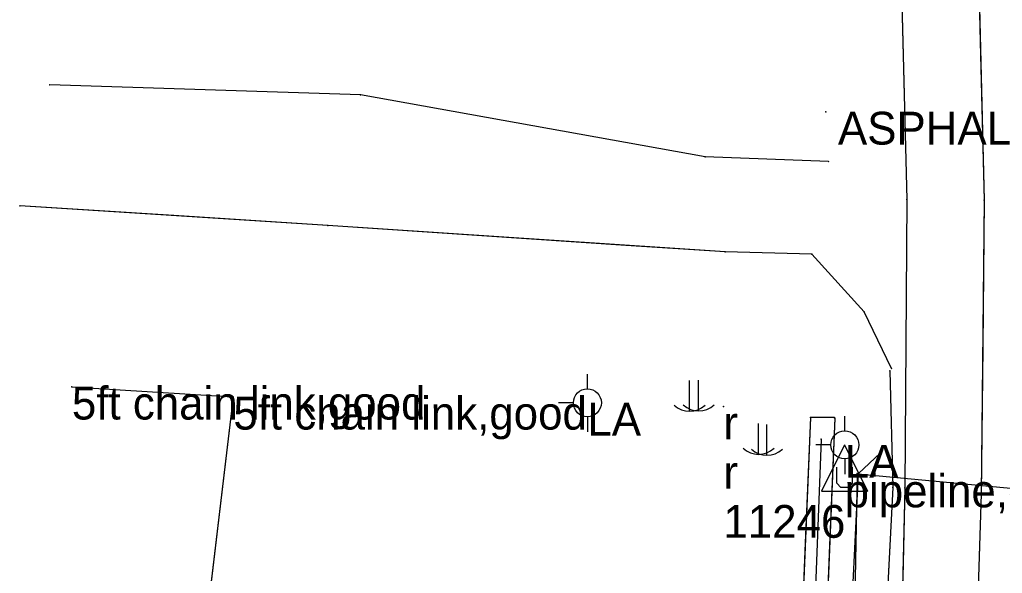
# Model space of a CAD drawing. Extents: x -99999 to 591807, y -99999 to 347168.
# Drawn here: x 591113.2 to 591263, y 320901.3 to 320985.6 of the extents above; entities that cross this region are included whole.
import ezdxf

# ---------------------------------------------------------------- set-up
doc = ezdxf.new("R2010")
doc.units = 0
for name, color, linetype in [('Default', 7, 'Continuous'), ('S_BREAKLINE', 7, 'Continuous'), ('S_DITCHLINE', 7, 'Continuous'), ('S_DRIVEWAY', 7, 'Continuous'), ('S_EDGE_PAVEMENT', 7, 'Continuous'), ('S_FENCE', 7, 'Continuous'), ('S_FENCE_ANNOT', 7, 'Continuous'), ('S_GAS_UTILITIES', 7, 'Continuous'), ('S_GRD_PT_SYM', 7, 'Continuous'), ('S_MSC_PT_SYM', 7, 'Continuous'), ('S_PARKING', 7, 'Continuous'), ('S_PAVEMENT_CROWN', 7, 'Continuous'), ('S_RDW_PT_SYM', 7, 'Continuous'), ('S_SHOULDER', 7, 'Continuous'), ('S_SIDEWALK', 7, 'Continuous'), ('S_SURVEY_TEXT_ANNOT', 7, 'Continuous'), ('S_UTILITY_POLE', 7, 'Continuous'), ('S_UTILITY_POLE_ANNOT', 7, 'Continuous'), ('S_UTL_PT_SYM', 7, 'Continuous'), ('S_WATER_UTILITIES', 7, 'Continuous')]:
    doc.layers.add(name, color=color, linetype=linetype)

msp = doc.modelspace()

# ---------------------------------------------------------------- linework, layer by layer
at = {"layer": 'Default'}
msp.add_lwpolyline([(591220.51, 320926.7), (591220.51, 320926.75), (591220.51, 320926.7), (591220.46, 320926.7), (591220.51, 320926.7), (591220.51, 320926.65), (591220.51, 320926.7), (591220.56, 320926.7)], dxfattribs=at)
at = {"layer": 'S_BREAKLINE'}
msp.add_lwpolyline([(591236.51, 320964.02), (591217.74, 320964.73), (591165.18, 320974.2), (591117.8, 320975.7)], dxfattribs=at)
at = {"layer": 'S_DITCHLINE'}
msp.add_lwpolyline([(591239.28, 320879.11), (591240.19, 320897.8), (591241.11, 320916.49), (591244.41, 320919.57)], dxfattribs=at)
at = {"layer": 'S_DRIVEWAY'}
msp.add_lwpolyline([(591246.15, 320932.47), (591241.98, 320941.14), (591233.98, 320949.92), (591220.76, 320950.28)], dxfattribs=at)
msp.add_lwpolyline([(591246.15, 320932.47), (591241.98, 320941.14), (591233.98, 320949.92), (591220.76, 320950.28)], dxfattribs=at)
at = {"layer": 'S_EDGE_PAVEMENT'}
for points in [[(591157.82, 321374.56), (591172, 321326.2), (591184.5, 321283.67), (591196.97, 321241.41), (591212.28, 321187.83), (591223.28, 321148.22), (591233.12, 321106.87), (591242.97, 321050.29), (591247.28, 321006.15), (591248.49, 320958.25), (591248.17, 320914.3), (591247.12, 320868.72), (591245.56, 320824.19), (591244.17, 320785.58), (591242.25, 320742.56), (591240.73, 320705.61), (591238.92, 320663.7), (591237.27, 320623.33), (591235.85, 320588.31), (591234.3, 320543.12), (591232.69, 320503.41), (591231.22, 320460.43), (591229.56, 320424.54)], [(591223.28, 321148.22), (591228.2, 321127.55), (591233.12, 321106.87), (591235.58, 321092.73), (591238.04, 321078.58), (591240.51, 321064.44), (591242.97, 321050.29), (591245.13, 321028.22), (591247.28, 321006.15), (591247.88, 320982.2), (591248.49, 320958.25), (591248.33, 320936.28), (591248.17, 320914.3), (591247.64, 320891.51)]]:
    msp.add_lwpolyline(points, dxfattribs=at)
at = {"layer": 'S_FENCE'}
for p, q in [((591121.19, 320929.72), (591145.8, 320928.19)), ((591145.8, 320928.19), (591140.22, 320881.7))]:
    msp.add_line(p, q, dxfattribs=at)
for points in [[(591121.19, 320929.72), (591145.8, 320928.19)], [(591145.8, 320928.19), (591140.22, 320881.7)]]:
    msp.add_lwpolyline(points, dxfattribs=at)
at = {"layer": 'S_GAS_UTILITIES'}
for p, q in [((591240.88, 320916.49), (591239.82, 320856.4)), ((591279.22, 320912.81), (591240.99, 320916.41))]:
    msp.add_line(p, q, dxfattribs=at)
at = {"layer": 'S_GRD_PT_SYM'}
for points in [[(591117.8, 320975.7), (591117.8, 320975.65), (591117.8, 320975.7), (591117.85, 320975.69), (591117.8, 320975.7), (591117.81, 320975.75), (591117.8, 320975.7), (591117.75, 320975.7)], [(591165.18, 320974.2), (591165.18, 320974.15), (591165.18, 320974.2), (591165.23, 320974.2), (591165.18, 320974.2), (591165.18, 320974.25), (591165.18, 320974.2), (591165.13, 320974.2)], [(591217.74, 320964.73), (591217.73, 320964.68), (591217.74, 320964.73), (591217.78, 320964.72), (591217.74, 320964.73), (591217.74, 320964.78), (591217.74, 320964.73), (591217.69, 320964.74)], [(591236.51, 320964.02), (591236.5, 320963.97), (591236.51, 320964.02), (591236.56, 320964.01), (591236.51, 320964.02), (591236.51, 320964.07), (591236.51, 320964.02), (591236.46, 320964.02)]]:
    msp.add_lwpolyline(points, close=True, dxfattribs=at)
at = {"layer": 'S_MSC_PT_SYM'}
for points in [[(591236.12, 320971.61), (591236.12, 320971.66), (591236.12, 320971.61), (591236.07, 320971.61), (591236.12, 320971.61), (591236.12, 320971.56), (591236.12, 320971.61), (591236.17, 320971.61)], [(591121.19, 320929.72), (591121.19, 320929.77), (591121.19, 320929.72), (591121.14, 320929.72), (591121.19, 320929.72), (591121.19, 320929.67), (591121.19, 320929.72), (591121.24, 320929.72)], [(591145.8, 320928.19), (591145.8, 320928.24), (591145.8, 320928.19), (591145.75, 320928.19), (591145.8, 320928.19), (591145.8, 320928.14), (591145.8, 320928.19), (591145.85, 320928.19)]]:
    msp.add_lwpolyline(points, dxfattribs=at)
for points in [[(591113.27, 320957.3), (591113.27, 320957.25), (591113.27, 320957.3), (591113.32, 320957.3), (591113.27, 320957.3), (591113.28, 320957.35), (591113.27, 320957.3), (591113.22, 320957.31)], [(591160.19, 320954.26), (591160.19, 320954.21), (591160.19, 320954.26), (591160.24, 320954.26), (591160.19, 320954.26), (591160.2, 320954.31), (591160.19, 320954.26), (591160.14, 320954.26)], [(591220.76, 320950.25), (591220.75, 320950.2), (591220.76, 320950.25), (591220.81, 320950.25), (591220.76, 320950.25), (591220.76, 320950.3), (591220.76, 320950.25), (591220.71, 320950.25)], [(591233.78, 320925.02), (591233.83, 320925.02), (591233.78, 320925.02), (591233.79, 320925.07), (591233.78, 320925.02), (591233.73, 320925.02), (591233.78, 320925.02), (591233.78, 320924.97)], [(591237.39, 320925.01), (591237.39, 320924.96), (591237.39, 320925.01), (591237.44, 320925.01), (591237.39, 320925.01), (591237.39, 320925.06), (591237.39, 320925.01), (591237.34, 320925.01)], [(591237.48, 320924.93), (591237.53, 320924.93), (591237.48, 320924.93), (591237.48, 320924.98), (591237.48, 320924.93), (591237.43, 320924.93), (591237.48, 320924.93), (591237.48, 320924.88)]]:
    msp.add_lwpolyline(points, close=True, dxfattribs=at)
at = {"layer": 'S_PARKING'}
for points in [[(591220.76, 320950.25), (591160.19, 320954.26), (591113.27, 320957.3)], [(591220.76, 320950.25), (591205.62, 320951.25), (591190.47, 320952.25), (591175.33, 320953.26), (591160.19, 320954.26), (591136.73, 320955.78), (591113.27, 320957.3)]]:
    msp.add_lwpolyline(points, dxfattribs=at)
at = {"layer": 'S_PAVEMENT_CROWN'}
for points in [[(591169.39, 321376.17), (591182.7, 321330.3), (591196.05, 321285.51), (591208.23, 321244.2), (591224.14, 321189.5), (591234.43, 321151.84), (591245.74, 321106.05), (591255.46, 321050.58), (591259.1, 321006.38), (591260.26, 320958.14), (591259.83, 320913.41), (591258.41, 320868.94), (591257.04, 320823.07), (591255.42, 320785.26), (591253.78, 320741.8), (591252.12, 320704.89), (591250.29, 320661.39), (591248.85, 320623.22), (591247.41, 320587.8), (591245.84, 320543.65), (591243.65, 320502.38), (591242.31, 320460.16), (591240.8, 320424.4)], [(591234.43, 321151.84), (591240.09, 321128.94), (591245.74, 321106.05), (591248.17, 321092.18), (591250.6, 321078.31), (591253.03, 321064.44), (591255.46, 321050.58), (591257.28, 321028.48), (591259.1, 321006.38), (591259.68, 320982.26), (591260.26, 320958.14), (591260.04, 320935.77), (591259.83, 320913.41), (591259.12, 320891.17)]]:
    msp.add_lwpolyline(points, dxfattribs=at)
at = {"layer": 'S_RDW_PT_SYM'}
for points in [[(591248.49, 320958.25), (591248.54, 320958.25), (591248.49, 320958.25), (591248.49, 320958.3), (591248.49, 320958.25), (591248.44, 320958.25), (591248.49, 320958.25), (591248.49, 320958.2)], [(591260.26, 320958.14), (591260.31, 320958.14), (591260.26, 320958.14), (591260.26, 320958.19), (591260.26, 320958.14), (591260.21, 320958.14), (591260.26, 320958.14), (591260.26, 320958.09)], [(591220.76, 320950.28), (591220.76, 320950.23), (591220.76, 320950.28), (591220.81, 320950.28), (591220.76, 320950.28), (591220.76, 320950.33), (591220.76, 320950.28), (591220.71, 320950.28)], [(591233.98, 320949.92), (591233.98, 320949.87), (591233.98, 320949.92), (591234.03, 320949.92), (591233.98, 320949.92), (591233.98, 320949.97), (591233.98, 320949.92), (591233.93, 320949.92)], [(591241.98, 320941.14), (591241.95, 320941.1), (591241.98, 320941.14), (591242.02, 320941.1), (591241.98, 320941.14), (591242.02, 320941.17), (591241.98, 320941.14), (591241.95, 320941.17)], [(591245.88, 320932.12), (591245.93, 320932.12), (591245.88, 320932.12), (591245.87, 320932.17), (591245.88, 320932.12), (591245.83, 320932.11), (591245.88, 320932.12), (591245.88, 320932.07)], [(591246.15, 320932.47), (591246.1, 320932.45), (591246.15, 320932.47), (591246.17, 320932.43), (591246.15, 320932.47), (591246.19, 320932.49), (591246.15, 320932.47), (591246.13, 320932.52)], [(591246.34, 320914.38), (591246.39, 320914.38), (591246.34, 320914.38), (591246.34, 320914.43), (591246.34, 320914.38), (591246.29, 320914.38), (591246.34, 320914.38), (591246.33, 320914.33)], [(591248.17, 320914.3), (591248.22, 320914.3), (591248.17, 320914.3), (591248.17, 320914.35), (591248.17, 320914.3), (591248.12, 320914.31), (591248.17, 320914.3), (591248.17, 320914.25)], [(591259.83, 320913.41), (591259.88, 320913.4), (591259.83, 320913.41), (591259.83, 320913.46), (591259.83, 320913.41), (591259.78, 320913.41), (591259.83, 320913.41), (591259.83, 320913.36)]]:
    msp.add_lwpolyline(points, close=True, dxfattribs=at)
at = {"layer": 'S_SHOULDER'}
for points in [[(591245.88, 320932.12), (591246.34, 320914.38), (591244.03, 320869.09), (591242.24, 320824.09), (591240.93, 320786.07), (591238.96, 320744.97), (591237.56, 320705.47), (591236.03, 320663.81), (591234.45, 320624.27), (591233.02, 320588.47), (591231.51, 320542.98), (591229.6, 320503.55), (591227.67, 320460.66), (591225.85, 320425.04)], [(591245.88, 320932.12), (591246.34, 320914.38), (591245.18, 320891.74)]]:
    msp.add_lwpolyline(points, dxfattribs=at)
at = {"layer": 'S_SIDEWALK'}
for points in [[(591237.39, 320925.01), (591233.78, 320925.02), (591232.19, 320886.82), (591231.95, 320879.54), (591220.06, 320881.05)], [(591237.39, 320925.01), (591233.78, 320925.02), (591232.99, 320905.92), (591232.19, 320886.82), (591231.95, 320879.54), (591220.06, 320881.05)], [(591237.48, 320924.93), (591235.93, 320886.27)], [(591237.48, 320924.93), (591236.71, 320905.6), (591235.93, 320886.27)]]:
    msp.add_lwpolyline(points, dxfattribs=at)
at = {"layer": 'S_UTILITY_POLE'}
for p, q in [((591199.78, 320929.38), (591199.78, 320931.63)), ((591215.3, 320930.69), (591215.3, 320925.96)), ((591216.69, 320930.74), (591216.69, 320926.01)), ((591197.69, 320927.25), (591195.36, 320927.25)), ((591199.86, 320922.84), (591199.86, 320925.16)), ((591239.02, 320922.97), (591239.02, 320925.21)), ((591225.82, 320924.12), (591225.82, 320919.39)), ((591227.09, 320923.98), (591227.09, 320919.25)), ((591236.93, 320920.84), (591234.6, 320920.84)), ((591238.99, 320920.88), (591235.47, 320913.79)), ((591238.99, 320920.88), (591242.48, 320913.79)), ((591239.1, 320916.42), (591239.1, 320918.74)), ((591237.79, 320915.03), (591237.79, 320917.47)), ((591240.16, 320917.47), (591240.16, 320915.03)), ((591238.41, 320914.37), (591237.79, 320915.03)), ((591239.61, 320914.37), (591238.41, 320914.37)), ((591240.16, 320915.03), (591239.61, 320914.37)), ((591235.47, 320913.79), (591242.48, 320913.79))]:
    msp.add_line(p, q, dxfattribs=at)
for centre in [(591199.78, 320927.27), (591239.02, 320920.86)]:
    msp.add_circle(centre, 2.13, dxfattribs=at)
for centre in [(591215.36, 320929.39), (591216.75, 320929.44), (591225.88, 320922.82), (591227.15, 320922.68)]:
    msp.add_arc(centre, 3.41, 226.3972, 313.6028, dxfattribs=at)
at = {"layer": 'S_UTL_PT_SYM'}
for points in [[(591235.44, 320921.72), (591235.44, 320921.77), (591235.44, 320921.72), (591235.39, 320921.72), (591235.44, 320921.72), (591235.44, 320921.67), (591235.44, 320921.72), (591235.49, 320921.72)], [(591240.88, 320916.49), (591240.88, 320916.54), (591240.88, 320916.49), (591240.83, 320916.49), (591240.88, 320916.49), (591240.88, 320916.44), (591240.88, 320916.49), (591240.93, 320916.49)], [(591240.99, 320916.41), (591240.99, 320916.46), (591240.99, 320916.41), (591240.94, 320916.41), (591240.99, 320916.41), (591240.99, 320916.36), (591240.99, 320916.41), (591241.04, 320916.41)]]:
    msp.add_lwpolyline(points, dxfattribs=at)
at = {"layer": 'S_WATER_UTILITIES'}
msp.add_line((591235.44, 320921.72), (591232.77, 320852.72), dxfattribs=at)

# ---------------------------------------------------------------- texts
at = {"layer": 'Default'}
for s, p in [('r', (591220.51, 320921.7)), ('r', (591220.51, 320914.2)), ('11246', (591220.51, 320906.7))]:
    msp.add_text(s, height=5, dxfattribs=at).set_placement(p)
at = {"layer": 'S_FENCE_ANNOT'}
for p in [(591121.19, 320924.72), (591145.8, 320923.19)]:
    msp.add_text('5ft chain link,good', height=5, dxfattribs=at).set_placement(p)
at = {"layer": 'S_SURVEY_TEXT_ANNOT'}
msp.add_text(' ASPHALT DW NO CUS', height=5, dxfattribs=at).set_placement((591236.12, 320966.61))
at = {"layer": 'S_UTILITY_POLE_ANNOT'}
for s, p in [('LA', (591199.78, 320922.27)), ('LA', (591239.02, 320915.86)), ('pipeline,gas,ar/ok gas corp.', (591238.99, 320911.34))]:
    msp.add_text(s, height=5, dxfattribs=at).set_placement(p)

doc.saveas('drawing.dxf')
